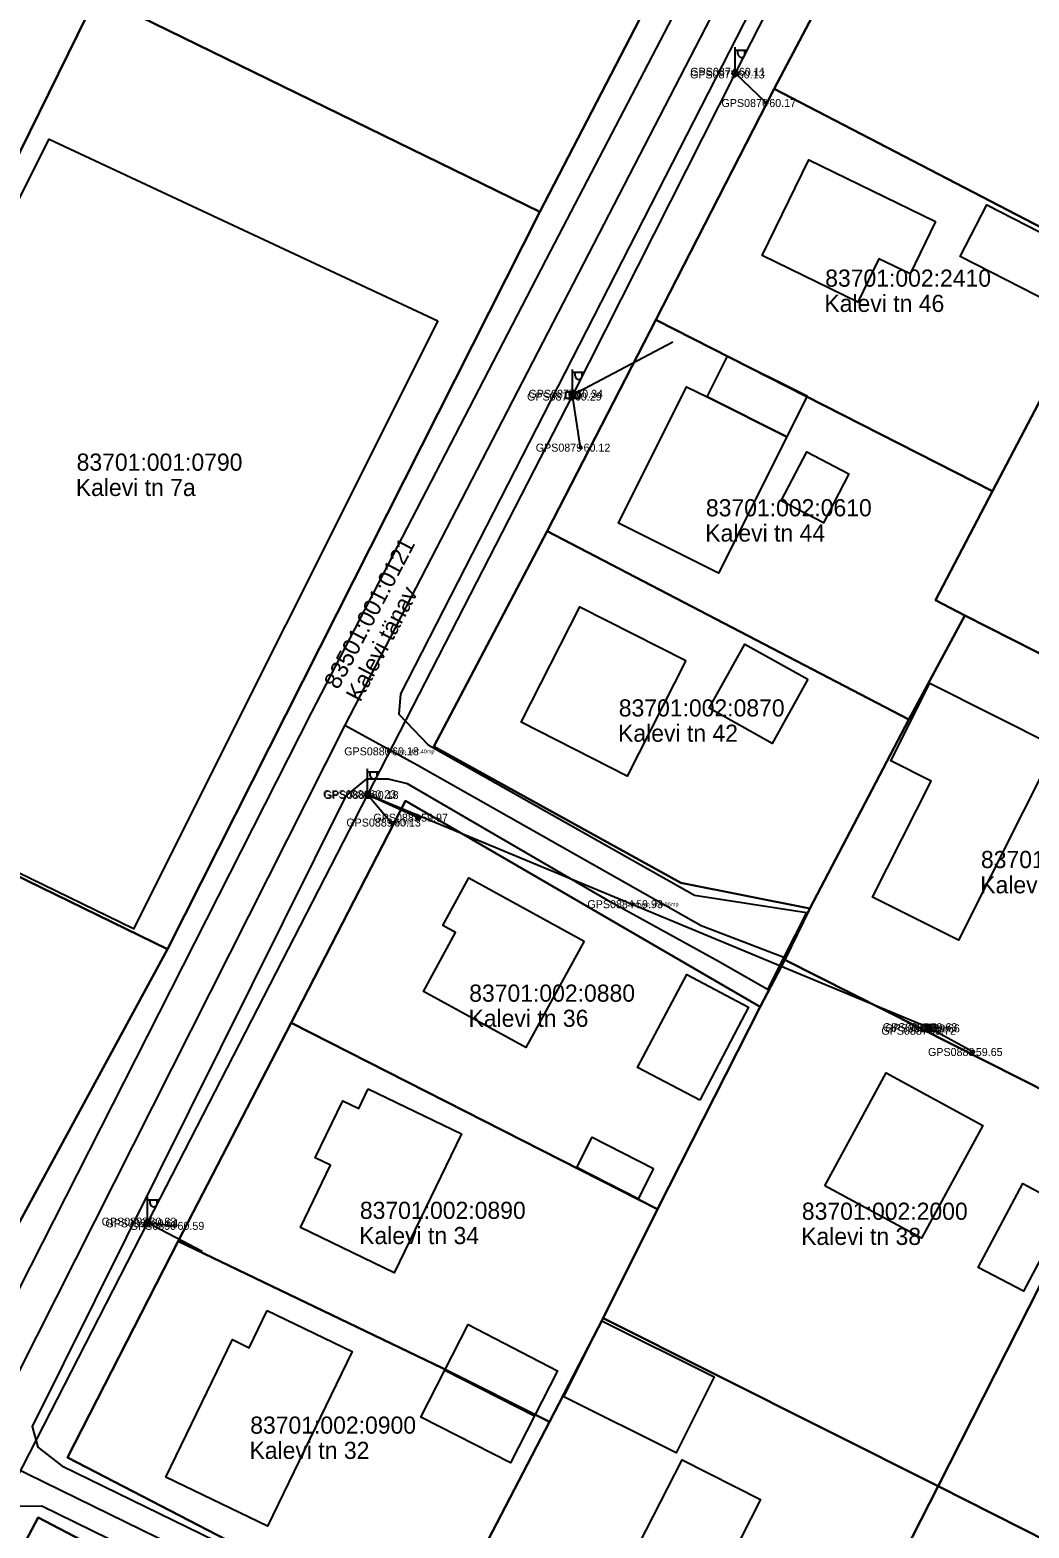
# Model space of a CAD drawing. Extents: x 580119 to 583377, y 6518915 to 6520820.
# Drawn here: x 581488.7 to 581576, y 6520226.6 to 6520357.7 of the extents above; entities that cross this region are included whole.
import ezdxf

# ---------------------------------------------------------------- set-up
doc = ezdxf.new("R2010")
doc.units = 0
for name, color, linetype in [('ELRAJATISMP', 7, 'Continuous'), ('Hoone Elu- või ühiskondlik hoone', 7, 'Continuous'), ('Hoone Kõrval- või tootmishoone', 7, 'Continuous'), ('L_AADRESS', 7, 'Continuous'), ('MAAMUDEL', 7, 'Continuous'), ('MOOTKORG-EH2000', 7, 'Continuous'), ('MOOTMPUNKT', 7, 'Continuous'), ('MOOTNR', 7, 'Continuous'), ('MPOHULIIN', 7, 'Continuous'), ('PIIR', 7, 'Continuous'), ('POST', 7, 'Continuous'), ('Rippe kõrgus', 7, 'Continuous'), ('SIOHULIIN', 7, 'Continuous'), ('Tee Liiklusala', 7, 'Continuous'), ('Tee Sport', 7, 'Continuous'), ('Tee Tänav Kruuskate', 7, 'Continuous'), ('Tee Tänav Püsikate', 7, 'Continuous'), ('TUNNUS', 7, 'Continuous')]:
    doc.layers.add(name, color=color, linetype=linetype)

msp = doc.modelspace()

# ---------------------------------------------------------------- linework, layer by layer
at = {"layer": 'ELRAJATISMP'}
for p, q in [((581535.99, 6520326.01), (581535.99, 6520325.41)), ((581536.27, 6520326.01), (581536.27, 6520325.41)), ((581567.15, 6520270.67), (581567.15, 6520270.07)), ((581567.42, 6520270.67), (581567.42, 6520270.07))]:
    msp.add_line(p, q, dxfattribs=at)
for points in [[(581535.53, 6520326.01), (581536.73, 6520326.01), (581536.73, 6520325.41), (581535.53, 6520325.41)], [(581566.68, 6520270.67), (581567.88, 6520270.67), (581567.88, 6520270.07), (581566.68, 6520270.07)]]:
    msp.add_lwpolyline(points, close=True, dxfattribs=at)
at = {"layer": 'Hoone Elu- või ühiskondlik hoone'}
for points in [[(581567.88, 6520340.9), (581565.65, 6520336.32), (581562.92, 6520337.65), (581561.08, 6520333.86), (581552.72, 6520337.92), (581556.78, 6520346.29)], [(581547.89, 6520325.56), (581554.86, 6520322.07), (581548.9, 6520310.14), (581540.14, 6520314.52), (581546.1, 6520326.45)], [(581546.03, 6520302.49), (581540.89, 6520292.39), (581531.63, 6520297.1), (581536.77, 6520307.2)], [(581578.39, 6520294.97), (581569.87, 6520278.02), (581562.37, 6520281.79), (581567.48, 6520291.95), (581563.95, 6520293.72), (581567.36, 6520300.51)], [(581537.14, 6520277.96), (581532.04, 6520268.65), (581523.08, 6520273.54), (581525.9, 6520278.7), (581524.78, 6520279.32), (581527.07, 6520283.48)], [(581558.2, 6520256.55), (581563.56, 6520266.42), (581572.01, 6520261.83), (581566.65, 6520251.96)], [(581518.26, 6520265.02), (581526.41, 6520261.08), (581520.54, 6520248.94), (581512.34, 6520252.9), (581514.97, 6520258.34), (581513.62, 6520259), (581516.03, 6520263.99), (581517.44, 6520263.32)], [(581509.41, 6520245.63), (581516.85, 6520242.04), (581509.46, 6520226.76), (581500.56, 6520231.07), (581506.38, 6520243.09), (581507.84, 6520242.38)], [(581553.94, 6520220.01), (581549.62, 6520211.55), (581540.77, 6520216.06), (581544.7, 6520223.74), (581541.93, 6520225.16), (581545.71, 6520232.58), (581552.56, 6520229.09), (581549.17, 6520222.44)]]:
    msp.add_lwpolyline(points, close=True, dxfattribs=at)
at = {"layer": 'Hoone Kõrval- või tootmishoone'}
for points in [[(581579.24, 6520338.83), (581582.96, 6520336.93), (581582.56, 6520336.15), (581580.63, 6520332.41), (581570.03, 6520337.85), (581572.34, 6520342.37)], [(581554.86, 6520322.07), (581547.89, 6520325.56), (581549.68, 6520329.12), (581556.65, 6520325.65)], [(581554.36, 6520316.46), (581556.6, 6520320.75), (581560.3, 6520318.82), (581558.06, 6520314.54)], [(581556.7, 6520300.88), (581553.57, 6520295.25), (581548.07, 6520298.32), (581551.2, 6520303.94)], [(581547.26, 6520264.05), (581541.81, 6520266.9), (581546.13, 6520275.02), (581551.51, 6520272.16), (581550.93, 6520271.07)], [(581543.22, 6520258.05), (581541.86, 6520255.4), (581536.49, 6520258.14), (581537.84, 6520260.79)], [(581579.43, 6520254.66), (581575.55, 6520247.32), (581571.6, 6520249.4), (581575.49, 6520256.74)], [(581532.79, 6520236.43), (581524.95, 6520240.43), (581526.99, 6520244.41), (581534.8, 6520240.37)], [(581535.37, 6520238.07), (581538.69, 6520244.73), (581548.51, 6520239.84), (581545.2, 6520233.18)], [(581532.79, 6520236.43), (581530.69, 6520232.32), (581522.86, 6520236.31), (581524.95, 6520240.43)]]:
    msp.add_lwpolyline(points, close=True, dxfattribs=at)
at = {"layer": 'MOOTMPUNKT'}
for centre in [(581550.32, 6520353.77), (581550.41, 6520354), (581553.07, 6520351.27), (581536.07, 6520325.59), (581536.19, 6520325.83), (581536.83, 6520321.12), (581520.08, 6520294.55), (581518.09, 6520290.8), (581518.31, 6520290.73), (581520.26, 6520288.32), (581522.63, 6520288.75), (581541.42, 6520281.18), (581567.05, 6520270.11), (581567.17, 6520270.42), (581567.39, 6520270.32), (581571.13, 6520268.25), (581498.87, 6520253.41), (581499.05, 6520253.26), (581501.32, 6520253.04)]:
    msp.add_circle(centre, 0.1, dxfattribs=at)
at = {"layer": 'MPOHULIIN'}
for p, q in [((581553.07, 6520351.27), (581550.36, 6520353.89)), ((581536.83, 6520321.12), (581536.13, 6520325.71)), ((581518.2, 6520290.77), (581520.26, 6520288.32)), ((581498.96, 6520253.33), (581501.32, 6520253.04))]:
    msp.add_line(p, q, dxfattribs=at)
for points in [[(581573.43, 6520394.97), (581563.99, 6520380.62), (581550.36, 6520353.89), (581536.13, 6520325.71), (581518.2, 6520290.77), (581498.96, 6520253.33), (581478.9, 6520214.22), (581458.59, 6520174.68)], [(581567.05, 6520270.11), (581567.28, 6520270.37), (581518.2, 6520290.77)]]:
    msp.add_lwpolyline(points, dxfattribs=at)
at = {"layer": 'PIIR'}
for points in [[(581400.45, 6520092.33), (581500.71, 6520277.24), (581533.26, 6520341.75), (581558.12, 6520389.79), (581657.24, 6520583.27)], [(581384.33, 6520418.25), (581405.05, 6520409.44), (581419.35, 6520443.1), (581449.24, 6520446.57), (581558.12, 6520389.79), (581533.26, 6520341.75), (581494.52, 6520360.71), (581462.65, 6520295.82), (581500.71, 6520277.24), (581400.45, 6520092.33)], [(581569.06, 6520381.55), (581553.75, 6520352.5), (581543.41, 6520332.3), (581533.92, 6520313.81), (581524.01, 6520294.98), (581545.6, 6520283.05), (581556.88, 6520280.8), (581554.68, 6520276.32), (581552.53, 6520272.21), (581521.51, 6520290.22), (581511.52, 6520270.81), (581501.63, 6520251.7), (581491.96, 6520232.77), (581521.41, 6520217.52)], [(581518.7, 6520212.19), (581489.39, 6520227.52), (581479.44, 6520208.7)]]:
    msp.add_lwpolyline(points, dxfattribs=at)
for points in [[(581569.06, 6520381.55), (581597.76, 6520366.89), (581583.28, 6520337.17), (581553.75, 6520352.5)], [(581500.71, 6520277.24), (581462.65, 6520295.82), (581494.52, 6520360.71), (581533.26, 6520341.75)], [(581553.75, 6520352.5), (581583.28, 6520337.17), (581582.45, 6520335.59), (581572.85, 6520317.31), (581543.41, 6520332.3)], [(581567.87, 6520307.79), (581572.85, 6520317.31), (581582.45, 6520335.59), (581609.05, 6520322), (581613.67, 6520319.49), (581599.4, 6520291.73), (581570.42, 6520306.43)], [(581543.41, 6520332.3), (581572.85, 6520317.31), (581567.87, 6520307.79), (581570.42, 6520306.43), (581565.52, 6520297.33), (581533.92, 6520313.81)], [(581533.92, 6520313.81), (581565.52, 6520297.33), (581556.88, 6520280.8), (581545.6, 6520283.05), (581524.01, 6520294.98)], [(581556.88, 6520280.8), (581565.52, 6520297.33), (581570.42, 6520306.43), (581599.4, 6520291.73), (581583.97, 6520261.52), (581554.68, 6520276.32)], [(581521.51, 6520290.22), (581552.53, 6520272.21), (581543.55, 6520254.5), (581511.52, 6520270.81)], [(581543.55, 6520254.5), (581552.53, 6520272.21), (581554.68, 6520276.32), (581583.97, 6520261.52), (581568.1, 6520230.26), (581538.79, 6520244.96)], [(581511.52, 6520270.81), (581543.55, 6520254.5), (581538.79, 6520244.96), (581534.1, 6520235.9), (581524.76, 6520240.58), (581501.63, 6520251.7)], [(581583.97, 6520261.52), (581613.05, 6520246.51), (581610.93, 6520241.82), (581597.19, 6520215.53), (581568.1, 6520230.26)], [(581501.63, 6520251.7), (581524.76, 6520240.58), (581534.1, 6520235.9), (581524.52, 6520217.43), (581521.41, 6520217.52), (581491.96, 6520232.77)], [(581528.82, 6520215.03), (581524.52, 6520217.43), (581534.1, 6520235.9), (581538.79, 6520244.96), (581568.1, 6520230.26), (581552.23, 6520199.15), (581527.23, 6520211.74)], [(581568.1, 6520230.26), (581597.19, 6520215.53), (581583.39, 6520188.69), (581581.01, 6520184.07), (581552.23, 6520199.15)], [(581489.39, 6520227.52), (581518.7, 6520212.19), (581518.89, 6520206.11), (581511.97, 6520192.31), (581479.44, 6520208.7)]]:
    msp.add_lwpolyline(points, close=True, dxfattribs=at)
at = {"layer": 'POST'}
for p, q in [((581550.36, 6520354.14), (581550.36, 6520356.14)), ((581550.36, 6520355.89), (581551.36, 6520355.89)), ((581550.59, 6520355.57), (581550.59, 6520355.89)), ((581551.2, 6520355.57), (581551.2, 6520355.89)), ((581550.36, 6520353.89), (581550.36, 6520353.89)), ((581536.13, 6520325.96), (581536.13, 6520327.96)), ((581536.13, 6520327.71), (581537.13, 6520327.71)), ((581536.36, 6520327.39), (581536.36, 6520327.71)), ((581536.97, 6520327.39), (581536.97, 6520327.71)), ((581536.13, 6520325.71), (581536.13, 6520325.71)), ((581518.2, 6520291.02), (581518.2, 6520293.02)), ((581518.2, 6520292.77), (581519.2, 6520292.77)), ((581518.43, 6520292.45), (581518.43, 6520292.77)), ((581519.04, 6520292.45), (581519.04, 6520292.77)), ((581518.2, 6520290.77), (581518.2, 6520290.77)), ((581498.96, 6520253.58), (581498.96, 6520255.58)), ((581498.96, 6520255.33), (581499.96, 6520255.33)), ((581499.19, 6520255.01), (581499.19, 6520255.33)), ((581499.8, 6520255.01), (581499.8, 6520255.33)), ((581498.96, 6520253.33), (581498.96, 6520253.33))]:
    msp.add_line(p, q, dxfattribs=at)
for points in [[(581518.2, 6520290.77), (581522.63, 6520288.75)], [(581571.13, 6520268.25), (581567.28, 6520270.37)]]:
    msp.add_lwpolyline(points, dxfattribs=at)
for centre, radius in [((581550.36, 6520353.89), 0.25), ((581536.13, 6520325.71), 0.25), ((581518.2, 6520290.77), 0.25), ((581522.63, 6520288.75), 0.2), ((581567.28, 6520270.37), 0.25), ((581571.13, 6520268.25), 0.125), ((581571.13, 6520268.25), 0.105), ((581571.13, 6520268.25), 0.0851), ((581571.13, 6520268.25), 0.0651), ((581571.13, 6520268.25), 0.0451), ((581571.13, 6520268.25), 0.0251), ((581571.13, 6520268.25), 0.00511), ((581498.96, 6520253.33), 0.25)]:
    msp.add_circle(centre, radius, dxfattribs=at)
for centre in [(581550.9, 6520355.57), (581536.66, 6520327.39), (581518.73, 6520292.45), (581499.49, 6520255.01)]:
    msp.add_arc(centre, 0.306, 180, 0, dxfattribs=at)
at = {"layer": 'SIOHULIIN'}
msp.add_lwpolyline([(581544.89, 6520330.36), (581536.13, 6520325.71), (581518.2, 6520290.77), (581498.96, 6520253.33), (581503.75, 6520250.82)], dxfattribs=at)
at = {"layer": 'Tee Liiklusala'}
for points in [[(581372.37, 6520277.77), (581412.75, 6520255.44), (581444.02, 6520238.01), (581474.39, 6520221.23), (581513.33, 6520297.97), (581534.24, 6520338.35), (581559.43, 6520386.73), (581591.38, 6520450.18), (581592.88, 6520453.16), (581609.8, 6520486.3), (581623.7, 6520512.67), (581636.83, 6520537.65), (581653.69, 6520569.75), (581656.07, 6520574.59), (581657.42, 6520577.86), (581657.31, 6520580.54), (581656.47, 6520584.5), (581655.72, 6520587.99), (581655.58, 6520589.38), (581654.54, 6520590.67), (581652.74, 6520592.05), (581631.26, 6520605.03)], [(581562.36, 6520380.26), (581521.08, 6520299.59), (581520.93, 6520297.81), (581523.51, 6520295.13), (581546.79, 6520281.98), (581556.58, 6520280.44), (581554.59, 6520276.55), (581553.18, 6520273.72), (581548.95, 6520276.14), (581539.41, 6520281.39), (581521.69, 6520291.7), (581520.03, 6520292.12), (581518.08, 6520292.12), (581516.3, 6520290.66), (581488.88, 6520235.48), (581489.36, 6520233.69), (581491.48, 6520232.04), (581521.93, 6520217.19)], [(581520.48, 6520213.45), (581489.72, 6520228.51), (581486.61, 6520228.5), (581484.66, 6520227.52), (581458.05, 6520176.72)]]:
    msp.add_lwpolyline(points, dxfattribs=at)
at = {"layer": 'Tee Sport'}
msp.add_lwpolyline([(581524.36, 6520332.21), (581497.73, 6520279.03), (581463.9, 6520295.5), (581490.35, 6520348.1)], close=True, dxfattribs=at)
at = {"layer": 'Tee Tänav Kruuskate'}
for points in [[(581516.22, 6520296.85), (581522.54, 6520293.38), (581547.36, 6520279.32), (581554.59, 6520276.55)], [(581484.21, 6520233.43), (581521.2, 6520215.32), (581523.09, 6520214.77), (581527.75, 6520213.4)]]:
    msp.add_lwpolyline(points, dxfattribs=at)
at = {"layer": 'Tee Tänav Püsikate'}
for points in [[(581561.96, 6520385.36), (581516.22, 6520296.85)], [(581516.22, 6520296.85), (581484.21, 6520233.43)]]:
    msp.add_lwpolyline(points, dxfattribs=at)

# ---------------------------------------------------------------- texts
at = {"layer": 'L_AADRESS'}
for s, p in [('Kalevi tn 46', (581558.15, 6520332.99)), ('Kalevi tn 7a', (581492.69, 6520316.89)), ('Kalevi tn 44', (581547.73, 6520312.9)), ('Kalevi tn 42', (581540.11, 6520295.39)), ('Kalevi tn 40', (581571.78, 6520282.13)), ('Kalevi tn 36', (581527.03, 6520270.45)), ('Kalevi tn 34', (581517.47, 6520251.44)), ('Kalevi tn 38', (581556.12, 6520251.37)), ('Kalevi tn 32', (581507.88, 6520232.65))]:
    msp.add_text(s, height=1.5, dxfattribs=at).set_placement(p)
msp.add_text('Kalevi tänav', height=1.5, rotation=62.2117, dxfattribs=at).set_placement((581517.56, 6520298.79))
at = {"layer": 'MAAMUDEL'}
for s, p in [(' mp_ohl', (581520.26, 6520288.14)), (' mp_ohl', (581567.05, 6520269.93)), (' kaabel', (581567.17, 6520270.24)), (' kaabel', (581567.39, 6520270.14))]:
    msp.add_text(s, height=0.35, dxfattribs=at).set_placement(p)
at = {"layer": 'MOOTKORG-EH2000'}
for s, p in [(' 60.13', (581550.32, 6520353.42)), (' 60.11', (581550.41, 6520353.65)), (' 60.17', (581553.07, 6520350.92)), (' 60.34', (581536.19, 6520325.48)), (' 60.29', (581536.07, 6520325.24)), (' 60.12', (581536.83, 6520320.77)), (' 60.18', (581520.08, 6520294.2)), (' 60.23', (581518.09, 6520290.45)), (' 60.18', (581518.31, 6520290.38)), (' 60.13', (581520.26, 6520287.97)), (' 59.97', (581522.63, 6520288.4)), (' 59.93', (581541.42, 6520280.83)), (' 59.72', (581567.05, 6520269.76)), (' 59.63', (581567.17, 6520270.07)), (' 59.66', (581567.39, 6520269.97)), (' 59.65', (581571.13, 6520267.9)), (' 60.63', (581498.87, 6520253.06)), (' 60.64', (581499.05, 6520252.91)), (' 60.59', (581501.32, 6520252.69))]:
    msp.add_text(s, height=0.7, dxfattribs=at).set_placement(p)
at = {"layer": 'MOOTNR'}
for s, p in [('GPS0875 ', (581546.4, 6520353.42)), ('GPS0874 ', (581546.42, 6520353.65)), ('GPS0876 ', (581549.15, 6520350.92)), ('GPS0877 ', (581532.27, 6520325.48)), ('GPS0878 ', (581532.15, 6520325.24)), ('GPS0879 ', (581532.91, 6520320.77)), ('GPS0880 ', (581516.16, 6520294.2)), ('GPS0881 ', (581514.31, 6520290.45)), ('GPS0882 ', (581514.39, 6520290.38)), ('GPS0889 ', (581516.34, 6520287.97)), ('GPS0883 ', (581518.71, 6520288.4)), ('GPS0884 ', (581537.43, 6520280.83)), ('GPS0887 ', (581563.13, 6520269.76)), ('GPS0885 ', (581563.25, 6520270.07)), ('GPS0886 ', (581563.47, 6520269.97)), ('GPS0888 ', (581567.21, 6520267.9)), ('GPS0892 ', (581494.95, 6520253.06)), ('GPS0891 ', (581495.28, 6520252.91)), ('GPS0890 ', (581497.4, 6520252.69))]:
    msp.add_text(s, height=0.7, dxfattribs=at).set_placement(p)
at = {"layer": 'Rippe kõrgus'}
for s, p in [(' el_mp_ohl7.40mp', (581520.08, 6520294.37)), (' el_mp_ohl5.85mp', (581541.42, 6520281))]:
    msp.add_text(s, height=0.35, dxfattribs=at).set_placement(p)
at = {"layer": 'TUNNUS'}
for s, p in [('83701:002:2410', (581558.22, 6520335.2)), ('83701:001:0790', (581492.76, 6520319.1)), ('83701:002:0610', (581547.79, 6520315.11)), ('83701:002:0870', (581540.17, 6520297.6)), ('83701:002:0570', (581571.84, 6520284.34)), ('83701:002:0880', (581527.09, 6520272.65)), ('83701:002:0890', (581517.53, 6520253.65)), ('83701:002:2000', (581556.18, 6520253.57)), ('83701:002:0900', (581507.94, 6520234.86))]:
    msp.add_text(s, height=1.5, dxfattribs=at).set_placement(p)
msp.add_text('83501:001:0121', height=1.5, rotation=62.2117, dxfattribs=at).set_placement((581515.64, 6520299.88))

doc.saveas('drawing.dxf')
